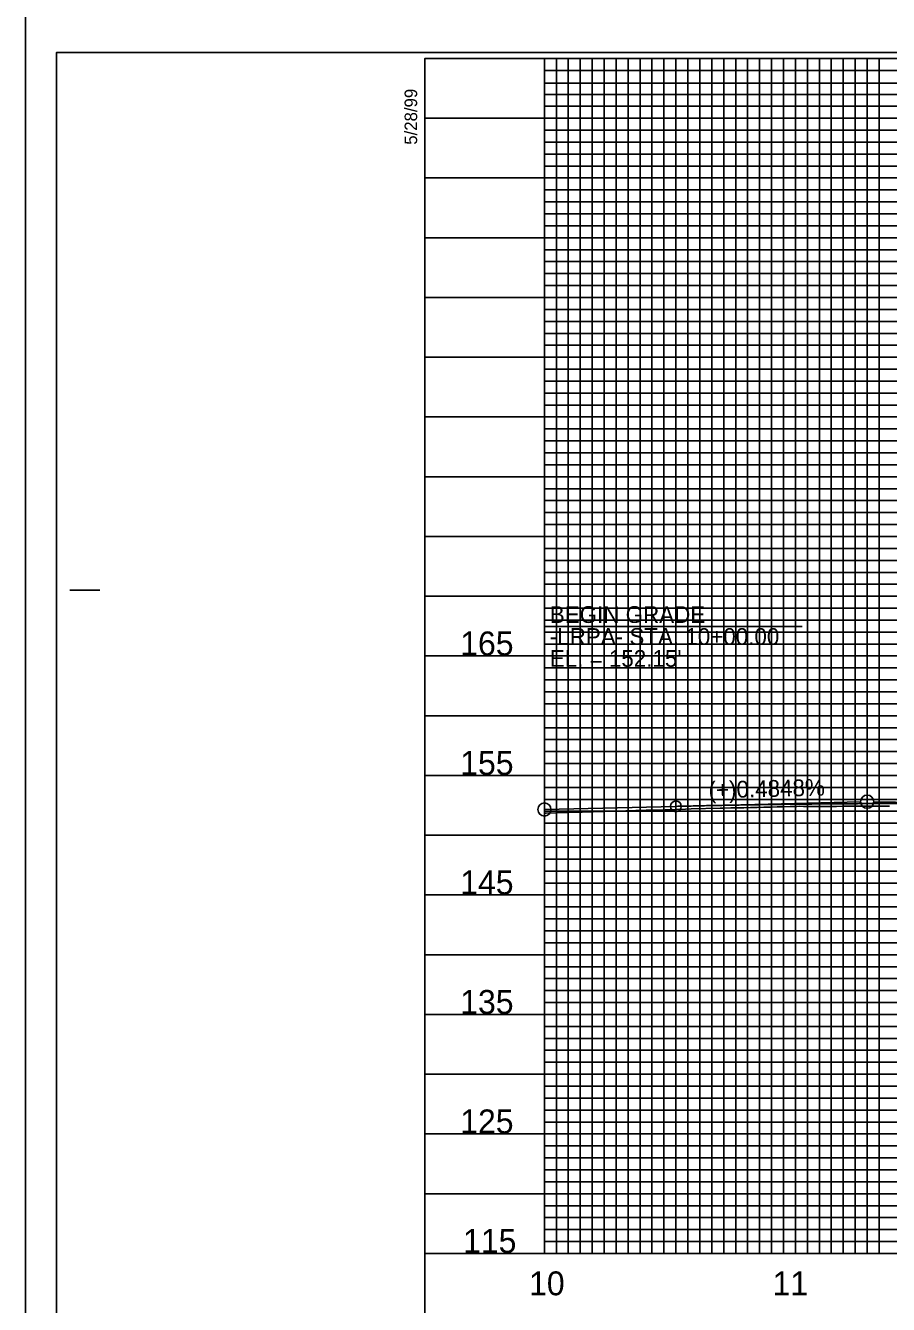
# Model space of a CAD drawing. Extents: x 573468 to 580768, y -57414 to -51768.
# Drawn here: x 578678 to 579039, y -53560 to -53025 of the extents above; entities that cross this region are included whole.
import ezdxf

# ---------------------------------------------------------------- set-up
doc = ezdxf.new("R2010")
doc.units = 0
for name, color, linetype in [('Exist Vertical Profile Ground Line', 7, 'Continuous'), ('Exist Vertical Profile Horizontal Axis Label Major', 7, 'Continuous'), ('Exist Vertical Profile Vertical Axis Label', 7, 'Continuous'), ('Prop PFL Text', 7, 'Continuous'), ('Prop Vertical Profile Curve Label', 7, 'Continuous'), ('Prop Vertical Profile Grade', 7, 'Continuous'), ('Prop Vertical Profile Grade Label', 7, 'Continuous'), ('Prop VPI Label', 7, 'Continuous'), ('Sheet Cutting Line CELL', 7, 'Continuous'), ('Sheet DOT Grid CELL', 7, 'Continuous'), ('Sheet Layout Profile Border Port 1', 7, 'Continuous'), ('Sheet Plot Border Inside CELL', 7, 'Continuous'), ('Sheet Plot Border Outside CELL', 7, 'Continuous'), ('Sheet Profile CELL', 7, 'Continuous'), ('Sheet Profile Grid Major CELL', 7, 'Continuous'), ('Sheet Profile Grid Middle CELL', 7, 'Continuous'), ('Sheet Profile Grid Minor CELL', 7, 'Continuous')]:
    doc.layers.add(name, color=color, linetype=linetype)

msp = doc.modelspace()

# ---------------------------------------------------------------- linework, layer by layer
at = {"layer": 'Exist Vertical Profile Ground Line'}
msp.add_lwpolyline([(578895.21, -53354.32), (578895.99, -53354.3), (578909.93, -53353.95), (578910.99, -53353.91), (578924.96, -53353.48), (578937.74, -53353.12), (578940.07, -53353.06), (578941.45, -53353.01), (578954.19, -53352.6), (578956.57, -53352.56), (578968.7, -53352.18), (578970.37, -53352.17), (578973.14, -53352.1), (578975.22, -53352.04), (578975.9, -53352.04), (578978.35, -53352.04), (578978.67, -53352.03), (578981.43, -53351.96), (578984.2, -53351.89), (578986.96, -53351.82), (578989.73, -53351.75), (578992.5, -53351.68), (578995.26, -53351.61), (578998.03, -53351.54), (579000.79, -53351.47), (579001.94, -53351.44), (579003.56, -53351.47), (579005.88, -53351.51), (579006.32, -53351.5), (579009.09, -53351.47), (579010.05, -53351.46), (579011.85, -53351.49), (579012.68, -53351.51), (579014.62, -53351.49), (579017.38, -53351.47), (579020.15, -53351.44), (579022.91, -53351.42), (579025.68, -53351.4), (579028.45, -53351.38), (579031.21, -53351.37), (579033.98, -53351.35), (579035.55, -53351.34), (579036.74, -53351.36), (579039.51, -53351.4)], dxfattribs=at)
at = {"layer": 'Prop PFL Text'}
for q in [(579002.97, -53276.25), (578895.21, -53352.8)]:
    msp.add_line((578895.21, -53276.25), q, dxfattribs=at)
at = {"layer": 'Prop Vertical Profile Curve Label'}
msp.add_circle((578950.21, -53351.47), 2.25, dxfattribs=at)
at = {"layer": 'Prop Vertical Profile Grade'}
msp.add_line((578895.21, -53352.8), (578950.21, -53351.47), dxfattribs=at)
msp.add_spline([(578950.21, -53351.47), (578953.41, -53351.39), (578956.61, -53351.32), (578959.81, -53351.25), (578963.01, -53351.18), (578966.21, -53351.11), (578969.41, -53351.05), (578972.61, -53350.99), (578975.81, -53350.93), (578979.01, -53350.87), (578982.21, -53350.82), (578985.41, -53350.77), (578988.61, -53350.72), (578991.81, -53350.67), (578995.01, -53350.63), (578998.21, -53350.59), (579001.41, -53350.55), (579004.61, -53350.52), (579007.81, -53350.48), (579011.01, -53350.45), (579014.21, -53350.43), (579017.41, -53350.4), (579020.61, -53350.38), (579023.81, -53350.36), (579027.01, -53350.34), (579030.21, -53350.32), (579033.41, -53350.31), (579036.61, -53350.3), (579039.81, -53350.29), (579043.01, -53350.29), (579046.21, -53350.29), (579049.41, -53350.29), (579052.61, -53350.29), (579055.81, -53350.3), (579059.01, -53350.3), (579062.21, -53350.31), (579065.41, -53350.33), (579068.61, -53350.34), (579071.81, -53350.36), (579075.01, -53350.38), (579078.21, -53350.41), (579081.41, -53350.43), (579084.61, -53350.46), (579087.81, -53350.49), (579091.01, -53350.52), (579094.21, -53350.56), (579097.41, -53350.6), (579100.61, -53350.64), (579103.81, -53350.68), (579107.01, -53350.73), (579110.21, -53350.78)], degree=3, dxfattribs=at)
at = {"layer": 'Prop VPI Label'}
for p, q in [((578950.21, -53351.47), (579027.47, -53349.59)), ((579110.21, -53350.78), (579032.96, -53349.57))]:
    msp.add_line(p, q, dxfattribs=at)
for centre in [(579030.21, -53349.53), (578895.21, -53352.8)]:
    msp.add_circle(centre, 2.75, dxfattribs=at)
at = {"layer": 'Sheet Cutting Line CELL'}
msp.add_line((578678.21, -53013.55), (578678.21, -54113.55), dxfattribs=at)
at = {"layer": 'Sheet DOT Grid CELL'}
for p, q in [((578895.21, -53538.55), (578895.21, -53038.55)), ((578945.21, -53538.55), (578945.21, -53038.55)), ((578995.21, -53538.55), (578995.21, -53038.55)), ((580145.16, -53088.55), (578845.21, -53088.55)), ((580145.16, -53138.55), (578845.21, -53138.55)), ((580345.21, -53188.55), (578845.21, -53188.55)), ((580345.21, -53238.55), (578845.21, -53238.55)), ((580345.21, -53288.55), (578845.21, -53288.55)), ((580345.21, -53338.55), (578845.21, -53338.55)), ((580345.21, -53388.55), (578845.21, -53388.55)), ((580345.21, -53438.55), (578845.21, -53438.55)), ((580345.21, -53488.55), (578845.21, -53488.55))]:
    msp.add_line(p, q, dxfattribs=at)
at = {"layer": 'Sheet Layout Profile Border Port 1'}
msp.add_lwpolyline([(578895.21, -53038.55), (578895.21, -53538.55), (580295.21, -53538.55), (580295.21, -53176.1), (580145.16, -53176.1), (580145.16, -53038.55)], close=True, dxfattribs=at)
at = {"layer": 'Sheet Plot Border Inside CELL'}
msp.add_lwpolyline([(578691.21, -54091.1), (580357.71, -54091.1), (580357.71, -53036), (578691.21, -53036)], close=True, dxfattribs=at)
at = {"layer": 'Sheet Plot Border Outside CELL'}
msp.add_lwpolyline([(578678.21, -54113.55), (580362.21, -54113.55), (580362.21, -53013.55), (578678.21, -53013.55)], close=True, dxfattribs=at)
at = {"layer": 'Sheet Profile CELL'}
for p, q in [((578696.71, -53261.05), (578709.21, -53261.05)), ((578845.21, -53538.55), (580345.21, -53538.55))]:
    msp.add_line(p, q, dxfattribs=at)
msp.add_lwpolyline([(580345.21, -53038.55), (578845.21, -53038.55), (578845.21, -54088.55), (580345.21, -54088.55)], close=True, dxfattribs=at)
at = {"layer": 'Sheet Profile Grid Major CELL'}
for points in [[(578895.21, -53038.55), (578895.21, -53538.55), (578945.21, -53538.55), (578945.21, -53038.55), (578995.21, -53038.55), (578995.21, -53538.55), (579045.21, -53538.55), (579045.21, -53038.55), (579095.21, -53038.55), (579095.21, -53538.55), (579145.21, -53538.55), (579145.21, -53038.55), (579195.21, -53038.55), (579195.21, -53538.55), (579245.21, -53538.55), (579245.21, -53038.55), (579295.21, -53038.55), (579295.21, -53538.55), (579345.21, -53538.55), (579345.21, -53038.55), (579395.21, -53038.55), (579395.21, -53538.55), (579445.21, -53538.55)], [(578845.21, -53088.55), (580145.21, -53088.55)], [(580145.21, -53138.55), (578845.21, -53138.55), (578845.21, -53188.55), (580345.21, -53188.55)], [(580345.21, -53238.55), (578845.21, -53238.55), (578845.21, -53288.55), (580345.21, -53288.55)], [(580345.21, -53338.55), (578845.21, -53338.55), (578845.21, -53388.55), (580345.21, -53388.55)], [(580345.21, -53438.55), (578845.21, -53438.55), (578845.21, -53438.55), (578845.21, -53488.55), (580345.21, -53488.55)]]:
    msp.add_lwpolyline(points, dxfattribs=at)
at = {"layer": 'Sheet Profile Grid Middle CELL'}
msp.add_line((578845.21, -53063.55), (580145.16, -53063.55), dxfattribs=at)
for points in [[(578920.21, -53038.55), (578920.21, -53538.55), (578970.21, -53538.55), (578970.21, -53038.55), (579020.21, -53038.55), (579020.21, -53538.55), (579070.21, -53538.55), (579070.21, -53038.55), (579120.21, -53038.55), (579120.21, -53538.55), (579170.21, -53538.55), (579170.21, -53038.55), (579220.21, -53038.55), (579220.21, -53538.55), (579270.21, -53538.55), (579270.21, -53038.55), (579320.21, -53038.55), (579320.21, -53538.55), (579370.21, -53538.55), (579370.21, -53038.55), (579420.21, -53038.55), (579420.21, -53538.55), (579470.21, -53538.55)], [(580145.21, -53113.55), (578845.21, -53113.55), (578845.21, -53163.55), (580145.21, -53163.55)], [(580345.21, -53213.55), (578845.21, -53213.55), (578845.21, -53263.55), (580170.21, -53263.55)], [(580345.21, -53313.55), (578845.21, -53313.55), (578845.21, -53363.55), (580345.21, -53363.55)], [(580345.21, -53413.55), (578845.21, -53413.55), (578845.21, -53463.55), (580345.21, -53463.55)], [(580345.21, -53513.55), (578845.21, -53513.55)]]:
    msp.add_lwpolyline(points, dxfattribs=at)
at = {"layer": 'Sheet Profile Grid Minor CELL'}
for p, q in [((578895.21, -53043.55), (580145.21, -53043.55)), ((578895.21, -53048.55), (578895.21, -53048.55)), ((580145.21, -53048.55), (578895.21, -53048.9)), ((578895.21, -53053.55), (580145.21, -53053.55)), ((580145.16, -53173.55), (578895.21, -53173.55)), ((580295.21, -53178.55), (578895.21, -53178.55)), ((580295.21, -53183.55), (578895.21, -53183.55)), ((578895.21, -53193.55), (580295.21, -53193.55)), ((580295.21, -53198.55), (578895.21, -53198.55)), ((578895.21, -53203.55), (580295.21, -53203.55)), ((580295.21, -53223.55), (578895.21, -53223.55)), ((578895.21, -53228.55), (580295.21, -53228.55)), ((580295.21, -53248.55), (578895.21, -53248.55)), ((578895.21, -53253.55), (580295.21, -53253.55)), ((580295.21, -53273.55), (578895.21, -53273.55)), ((578895.21, -53278.55), (580295.21, -53278.55)), ((580295.21, -53283.55), (578895.21, -53283.55)), ((578895.21, -53293.55), (580295.21, -53293.55)), ((580295.21, -53298.55), (578895.21, -53298.55)), ((578895.21, -53303.55), (580295.21, -53303.55)), ((580295.21, -53308.55), (578895.21, -53308.55)), ((578895.21, -53318.55), (580295.21, -53318.55)), ((580295.21, -53323.55), (578895.21, -53323.55)), ((578895.21, -53328.55), (580295.21, -53328.55)), ((580295.21, -53333.55), (578895.21, -53333.55)), ((578895.21, -53343.55), (580295.21, -53343.55)), ((580295.21, -53348.55), (578895.21, -53348.55)), ((578895.21, -53353.55), (580295.21, -53353.55)), ((580295.21, -53358.55), (578895.21, -53358.55)), ((578895.21, -53368.55), (580295.21, -53368.55)), ((580295.21, -53373.55), (578895.21, -53373.55)), ((578895.21, -53378.55), (580295.21, -53378.55)), ((580295.21, -53383.55), (578895.21, -53383.55)), ((578895.21, -53393.55), (580295.21, -53393.55)), ((580295.21, -53398.55), (578895.21, -53398.55)), ((578895.21, -53403.55), (580295.21, -53403.55)), ((580295.21, -53408.55), (578895.21, -53408.55)), ((578895.21, -53418.55), (580295.21, -53418.55)), ((580295.21, -53423.55), (578895.21, -53423.55)), ((580295.21, -53428.55), (578895.21, -53428.55)), ((580295.21, -53433.55), (578895.21, -53433.55)), ((578895.21, -53443.55), (580295.21, -53443.55)), ((580295.21, -53448.55), (578895.21, -53448.55)), ((578895.21, -53453.55), (580295.21, -53453.55)), ((580295.21, -53458.55), (578895.21, -53458.55)), ((578895.21, -53468.55), (580295.21, -53468.55)), ((580295.21, -53473.55), (578895.21, -53473.55)), ((578895.21, -53478.55), (580295.21, -53478.55)), ((580295.21, -53483.55), (578895.21, -53483.55)), ((578895.21, -53493.55), (580295.21, -53493.55)), ((580295.21, -53498.55), (578895.21, -53498.55)), ((578895.21, -53503.55), (580295.21, -53503.55)), ((580295.21, -53508.55), (578895.21, -53508.55)), ((578895.21, -53518.55), (580295.21, -53518.55)), ((580295.21, -53523.55), (578895.21, -53523.55)), ((578895.21, -53528.55), (580295.21, -53528.55))]:
    msp.add_line(p, q, dxfattribs=at)
for points in [[(578900.21, -53038.55), (578900.21, -53538.55), (578905.21, -53538.55), (578905.21, -53038.55), (578910.21, -53038.55), (578910.21, -53538.55), (578915.21, -53538.55), (578915.21, -53038.55), (578925.21, -53038.55), (578925.21, -53538.55), (578930.21, -53538.55), (578930.21, -53038.55), (578935.21, -53038.55), (578935.21, -53538.55), (578940.21, -53538.55), (578950.21, -53538.55), (578955.21, -53538.55), (578955.21, -53038.55), (578960.21, -53038.55), (578960.21, -53538.55), (578965.21, -53538.55), (578965.21, -53038.55), (578975.21, -53038.55), (578975.21, -53538.55), (578980.21, -53538.55), (578980.21, -53038.55), (578985.21, -53038.55), (578985.21, -53538.55), (578990.21, -53538.55), (578990.21, -53038.55), (579000.21, -53038.55), (579000.21, -53538.55), (579005.21, -53538.55), (579005.21, -53038.55), (579010.21, -53038.55), (579010.21, -53538.55), (579015.21, -53538.55), (579015.21, -53038.55), (579025.21, -53038.55), (579025.21, -53538.55), (579030.21, -53538.55), (579030.21, -53038.55), (579035.21, -53038.55), (579035.21, -53538.55), (579040.21, -53538.55)], [(578940.21, -53538.55), (578940.21, -53038.55), (578950.21, -53038.55), (578950.21, -53538.55)], [(580145.21, -53058.55), (578895.21, -53058.55), (578895.21, -53068.55), (580145.21, -53068.55)], [(580145.16, -53073.55), (578895.21, -53073.55), (578895.21, -53078.55), (580145.21, -53078.55)], [(580145.21, -53083.55), (578895.21, -53083.55), (578895.21, -53093.55), (580145.21, -53093.55)], [(580145.21, -53098.55), (578895.21, -53098.55), (578895.21, -53103.55), (580145.21, -53103.55)], [(580145.21, -53108.55), (578895.21, -53108.55), (578895.21, -53118.55), (580145.21, -53118.55)], [(580145.21, -53123.55), (578895.21, -53123.55), (578895.21, -53128.55), (580145.21, -53128.55)], [(580145.21, -53133.55), (578895.21, -53133.55), (578895.21, -53143.55), (580145.21, -53143.55)], [(580145.21, -53148.65), (578895.31, -53148.65), (578895.31, -53153.55), (580145.21, -53153.55)], [(580145.21, -53158.55), (578895.21, -53158.55), (578895.21, -53168.55), (580145.21, -53168.55)], [(580295.21, -53208.55), (578895.21, -53208.55), (578895.21, -53218.55), (580295.21, -53218.55)], [(580295.21, -53233.55), (578895.21, -53233.55), (578895.21, -53243.55), (580295.21, -53243.55)], [(580295.21, -53258.55), (578895.21, -53258.55), (578895.21, -53268.55), (580295.21, -53268.55)], [(580295.21, -53533.55), (578895.21, -53533.55)]]:
    msp.add_lwpolyline(points, dxfattribs=at)

# ---------------------------------------------------------------- texts
at = {"layer": 'Exist Vertical Profile Horizontal Axis Label Major'}
for s, p in [('10', (578888.8, -53556.05)), ('11', (578990.64, -53556.05))]:
    msp.add_text(s, height=10, dxfattribs=at).set_placement(p)
at = {"layer": 'Exist Vertical Profile Vertical Axis Label'}
for s, p in [('165', (578860, -53288.3)), ('155', (578860, -53338.3)), ('145', (578860, -53388.3)), ('135', (578860, -53438.3)), ('125', (578860, -53488.3)), ('115', (578861.2, -53538.3))]:
    msp.add_text(s, height=10, dxfattribs=at).set_placement(p)
at = {"layer": 'Prop PFL Text'}
for s, p in [('BEGIN GRADE', (578897.46, -53274.72)), ('-LRPA- STA. 10+00.00', (578897.46, -53283.9)), ("EL. = 152.15'", (578897.46, -53293.07))]:
    msp.add_text(s, height=7, dxfattribs=at).set_placement(p)
at = {"layer": 'Prop Vertical Profile Grade Label'}
msp.add_text('(+)0.4848%', height=7, rotation=1.3886, dxfattribs=at).set_placement((578963.94, -53348.13))
at = {"layer": 'Sheet Profile CELL'}
msp.add_text('5/28/99', height=5.25, rotation=90, dxfattribs=at).set_placement((578841.98, -53074.64))

doc.saveas('drawing.dxf')
